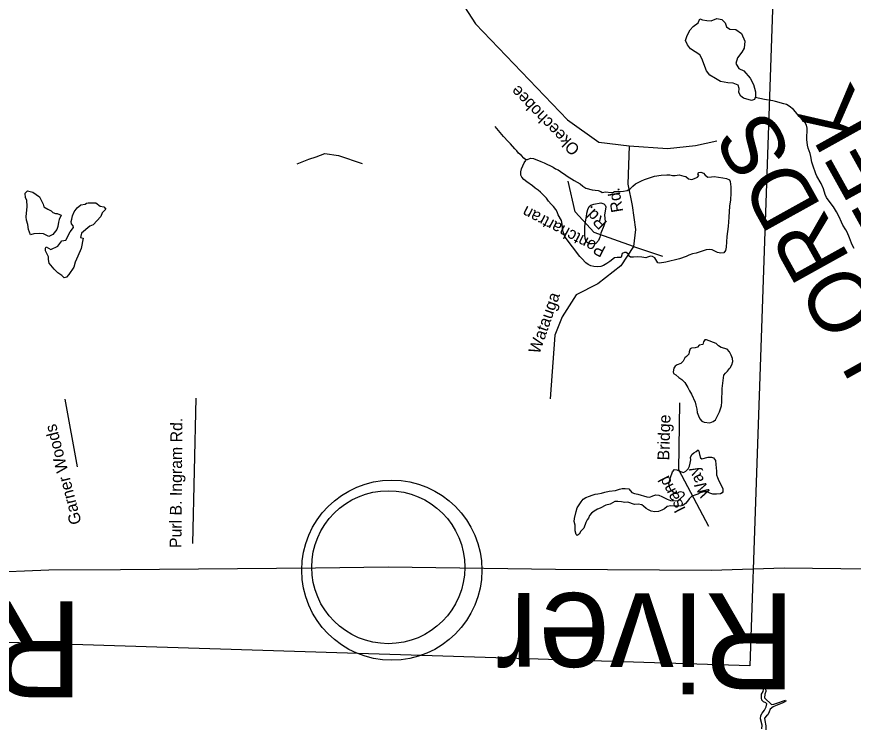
# Model space of a CAD drawing. Extents: x 2308163 to 2335412, y -96774 to 127732.
# Drawn here: x 2326125 to 2326219, y 122972.3 to 123052.3 of the extents above; entities that cross this region are included whole.
import ezdxf

# ---------------------------------------------------------------- set-up
doc = ezdxf.new("R2010")
doc.units = 0
for name, color, linetype in [('Default', 7, 'Continuous'), ('Old_Level_10', 7, 'Continuous'), ('Old_Level_11', 7, 'Continuous'), ('Old_Level_21', 7, 'Continuous'), ('Old_Level_32', 7, 'Continuous'), ('Old_Level_35', 7, 'Continuous'), ('Old_Level_59', 7, 'Continuous'), ('Old_Level_60', 7, 'Continuous'), ('Old_Level_61', 7, 'Continuous'), ('Old_Level_63', 7, 'Continuous')]:
    doc.layers.add(name, color=color, linetype=linetype)

msp = doc.modelspace()

# ---------------------------------------------------------------- linework, layer by layer
at = {"layer": 'Default'}
for centre, radius in [((2326167.157, 122990.014), 10.125), ((2326166.763, 122990.349), 8.606)]:
    msp.add_circle(centre, radius, dxfattribs=at)
at = {"layer": 'Old_Level_32'}
msp.add_lwpolyline([(2326240.144, 122990.411), (2326235.44, 122990.153), (2326232.787, 122990.142), (2326230.334, 122990.023), (2326211.264, 122990.222), (2326203.095, 122989.994), (2326185.551, 122990.089), (2326166.763, 122990.349), (2326158.564, 122990.222), (2326136.661, 122990.068), (2326128.602, 122990.027), (2326121.262, 122989.724), (2326120.231, 122989.721), (2326117.665, 122989.676)], dxfattribs=at)
at = {"layer": 'Old_Level_35'}
for points in [[(2326180.095, 123068.715), (2326178.579, 123066.219), (2326174.393, 123060.305), (2326173.511, 123057.806), (2326173.742, 123055.862), (2326176.57, 123051.446), (2326186.927, 123040.665), (2326190.418, 123038.162), (2326193.831, 123037.746), (2326198.142, 123037.449), (2326201.283, 123037.787), (2326203.685, 123038.3)], [(2326193.831, 123037.746), (2326193.682, 123033.433), (2326194.195, 123031.032), (2326194.549, 123028.34), (2326194.334, 123026.411), (2326192.917, 123024.226), (2326190.315, 123022.231), (2326187.888, 123020.975), (2326186.312, 123018.498), (2326185.496, 123016.441), (2326184.946, 123009.301)], [(2326156.532, 123035.701), (2326157.816, 123036.257), (2326158.664, 123036.518), (2326159.643, 123036.865), (2326161.161, 123036.665), (2326163.835, 123035.737)], [(2326194.334, 123026.411), (2326189.918, 123027.993), (2326187.762, 123030.301), (2326186.987, 123033.753)], [(2326194.334, 123026.411), (2326197.576, 123025.346)], [(2326131.815, 123001.644), (2326130.456, 123009.252)], [(2326144.78, 122993.006), (2326145.178, 123009.344)], [(2326202.786, 122994.937), (2326199.429, 123001.307), (2326199.531, 123008.825)]]:
    msp.add_lwpolyline(points, dxfattribs=at)
at = {"layer": 'Old_Level_59'}
for points in [[(2326217.159, 123030.315), (2326216.819, 123030.881), (2326216.192, 123031.68), (2326216.022, 123031.94), (2326215.883, 123032.249), (2326215.69, 123032.906), (2326215.417, 123033.495), (2326214.94, 123034.314), (2326214.813, 123034.603), (2326214.485, 123035.56), (2326214.393, 123035.913), (2326214.272, 123036.532), (2326214.188, 123036.865), (2326213.976, 123037.488), (2326213.902, 123037.815), (2326213.826, 123038.438), (2326213.84, 123039.728), (2326213.771, 123040.045), (2326213.616, 123040.325), (2326213.407, 123040.566), (2326212.944, 123041.044), (2326212.531, 123041.562), (2326212.3, 123041.808), (2326211.82, 123042.206), (2326211.537, 123042.384), (2326211.234, 123042.48), (2326210.305, 123042.721), (2326209.98, 123042.793), (2326209.058, 123042.936), (2326208.011, 123043.175)], [(2326182.201, 123036.19), (2326181.987, 123036.365), (2326181.731, 123036.659), (2326181.415, 123036.919), (2326181.222, 123037.174), (2326180.972, 123037.406), (2326180.513, 123037.956), (2326180.232, 123038.225), (2326179.697, 123038.797), (2326178.766, 123039.901)], [(2326219.117, 123026.198), (2326218.972, 123026.472), (2326218.84, 123026.787), (2326218.616, 123027.409), (2326218.338, 123028.018), (2326218.199, 123028.297), (2326217.868, 123028.822), (2326217.704, 123029.138), (2326217.443, 123029.751), (2326217.159, 123030.315)]]:
    msp.add_lwpolyline(points, dxfattribs=at)
at = {"layer": 'Old_Level_60'}
for points in [[(2326208.011, 123043.175), (2326207.928, 123042.94), (2326207.604, 123042.834), (2326206.696, 123043.094), (2326206.381, 123043.329), (2326206.151, 123043.743), (2326206.205, 123044.168), (2326206.084, 123044.553), (2326205.514, 123044.781), (2326204.947, 123044.836), (2326204.106, 123044.962), (2326203.563, 123045.321), (2326202.902, 123045.7), (2326202.517, 123046.165), (2326201.998, 123047.555), (2326201.777, 123047.984), (2326200.717, 123048.641), (2326200.415, 123049.098), (2326200.188, 123049.589), (2326200.346, 123050.157), (2326200.716, 123050.8), (2326201.035, 123051.15), (2326201.58, 123051.578), (2326201.767, 123052.039), (2326202.086, 123051.911), (2326202.589, 123051.823), (2326203.065, 123051.796), (2326203.707, 123052.069), (2326204.243, 123051.939), (2326204.624, 123051.56), (2326204.8, 123051.112), (2326205.173, 123050.85), (2326205.814, 123050.817), (2326206.453, 123050.374), (2326206.832, 123049.512), (2326206.776, 123048.721), (2326206.515, 123048.283), (2326206.013, 123047.64), (2326205.845, 123047.006), (2326206.167, 123046.451), (2326206.747, 123046.177), (2326207.44, 123045.345), (2326207.822, 123044.625), (2326208.05, 123043.82), (2326208.041, 123043.261), (2326208.011, 123043.175)], [(2326182.201, 123036.19), (2326182.424, 123036.198), (2326182.733, 123036.37), (2326183.068, 123036.308), (2326183.905, 123035.984), (2326184.275, 123035.824), (2326185.309, 123035.321), (2326185.569, 123035.159), (2326185.853, 123035.023), (2326186.124, 123034.866), (2326186.732, 123034.454), (2326186.977, 123034.262), (2326187.359, 123034.026), (2326187.671, 123033.857), (2326188.327, 123033.449), (2326188.626, 123033.21), (2326188.961, 123032.98), (2326189.677, 123032.797), (2326190.364, 123032.697), (2326190.672, 123032.6), (2326190.8, 123032.479), (2326191.193, 123032.562), (2326191.821, 123032.5), (2326191.998, 123032.504), (2326192.196, 123032.589), (2326192.852, 123032.591), (2326193.213, 123032.625), (2326193.629, 123032.702), (2326193.984, 123032.923), (2326194.242, 123033.209), (2326194.552, 123033.478), (2326195.219, 123033.805), (2326195.553, 123033.936), (2326195.915, 123034.051), (2326196.245, 123034.192), (2326196.701, 123034.339), (2326197.422, 123034.431), (2326198.064, 123034.485), (2326198.409, 123034.478), (2326198.706, 123034.407), (2326199.03, 123034.395), (2326199.445, 123034.462), (2326199.73, 123034.412), (2326200.003, 123034.316), (2326200.222, 123034.293), (2326200.505, 123034.03), (2326200.873, 123033.956), (2326201.175, 123034.047), (2326201.508, 123034.224), (2326201.672, 123034.386), (2326201.561, 123034.572), (2326201.686, 123034.726), (2326201.902, 123034.794), (2326202.18, 123034.663), (2326202.396, 123034.447), (2326202.676, 123034.214), (2326203.08, 123034.235), (2326203.413, 123034.29), (2326204.371, 123034.155), (2326204.789, 123034.07), (2326205.112, 123033.896), (2326205.212, 123033.715), (2326205.285, 123033.128), (2326205.268, 123032.397), (2326205.215, 123031.677), (2326205.137, 123030.948), (2326205.052, 123029.732), (2326204.961, 123028.683), (2326204.837, 123027.554), (2326204.738, 123026.348), (2326204.682, 123025.964), (2326204.498, 123025.686), (2326204.133, 123025.663), (2326203.783, 123025.746), (2326203.468, 123025.879), (2326203.167, 123026.047), (2326202.841, 123026.083), (2326202.484, 123026.035), (2326201.374, 123025.677), (2326200.956, 123025.584), (2326200.563, 123025.435), (2326200.23, 123025.279), (2326199.504, 123025.02), (2326197.979, 123024.666), (2326197.238, 123024.549), (2326197.053, 123024.566), (2326196.744, 123025.14), (2326196.452, 123025.298), (2326196.238, 123025.335), (2326195.92, 123025.235), (2326195.718, 123025.15), (2326195.259, 123025.232), (2326194.801, 123025.273), (2326194.342, 123025.218), (2326193.995, 123025.23), (2326193.842, 123025.347), (2326193.797, 123025.516), (2326193.49, 123025.725), (2326193.304, 123025.752), (2326193.069, 123025.618)], [(2326193.069, 123025.618), (2326192.95, 123025.23), (2326192.881, 123025.167), (2326192.497, 123025.17), (2326192.197, 123025.14), (2326191.683, 123024.73), (2326191.337, 123024.493), (2326190.944, 123024.294), (2326190.637, 123024.172), (2326190.276, 123024.139), (2326189.877, 123024.163), (2326189.524, 123024.246), (2326189.224, 123024.378), (2326188.981, 123024.58), (2326188.507, 123025.053), (2326188.3, 123025.289), (2326186.66, 123027.475), (2326186.497, 123027.826), (2326186.374, 123028.191), (2326186.353, 123028.598), (2326186.308, 123028.935), (2326186.218, 123029.334), (2326185.871, 123029.987), (2326185.751, 123030.301), (2326185.587, 123030.591), (2326185.346, 123030.914), (2326185.06, 123031.183), (2326184.791, 123031.497), (2326184.542, 123031.846), (2326183.885, 123032.514), (2326183.62, 123032.747), (2326183.256, 123032.983), (2326182.961, 123033.253), (2326182.323, 123033.686), (2326182.009, 123033.936), (2326181.765, 123034.224), (2326181.646, 123034.446), (2326181.679, 123034.806), (2326181.756, 123035.149), (2326181.888, 123035.495), (2326182.044, 123035.835), (2326182.208, 123036.104), (2326182.201, 123036.19)], [(2326135.018, 123030.6), (2326134.588, 123030.199), (2326134.463, 123029.773), (2326133.585, 123028.861), (2326133.205, 123028.707), (2326132.275, 123027.907), (2326132.175, 123027.411), (2326132.451, 123027.36), (2326132.229, 123026.175), (2326131.867, 123025.314), (2326131.566, 123024.658), (2326131.423, 123024.108), (2326130.852, 123023.254), (2326130.579, 123022.986), (2326130.34, 123022.898), (2326130.072, 123023.17), (2326129.624, 123023.463), (2326129.208, 123023.88), (2326128.635, 123024.551), (2326128.565, 123024.942), (2326128.562, 123025.261), (2326128.224, 123025.925), (2326128.234, 123026.216), (2326128.31, 123026.393), (2326128.813, 123026.085), (2326129.603, 123026.46), (2326130.081, 123027.053), (2326130.5, 123027.136), (2326130.989, 123028.049), (2326131.368, 123028.563), (2326131.347, 123028.757), (2326131.16, 123028.972), (2326131.114, 123029.237), (2326131.178, 123029.498), (2326131.247, 123029.87), (2326131.442, 123030.308), (2326131.791, 123030.781), (2326132.19, 123031.086), (2326132.693, 123031.18), (2326132.822, 123031.3), (2326133.018, 123031.335), (2326133.906, 123031.332), (2326134.392, 123030.941), (2326134.778, 123030.872), (2326135.018, 123030.6)], [(2326205.482, 123013.493), (2326205.447, 123013.839), (2326205.305, 123014.21), (2326205.114, 123014.552), (2326204.865, 123014.866), (2326204.169, 123015.072), (2326203.89, 123015.255), (2326203.624, 123015.503), (2326202.527, 123015.922), (2326202.339, 123015.933), (2326202.199, 123015.709), (2326202.135, 123015.407), (2326201.702, 123015.32), (2326201.515, 123015.083), (2326201.278, 123015.01), (2326200.861, 123014.999), (2326200.69, 123014.913), (2326200.577, 123014.587), (2326200.545, 123014.308), (2326200.276, 123014.053), (2326200.092, 123013.902), (2326199.926, 123013.527), (2326199.663, 123013.251), (2326199.247, 123013.098), (2326198.996, 123012.944), (2326198.874, 123012.725), (2326198.802, 123012.331), (2326198.842, 123012.152), (2326199.092, 123011.97), (2326199.412, 123011.695), (2326199.764, 123011.469), (2326200.105, 123011.112), (2326200.442, 123010.552), (2326200.614, 123010.175), (2326200.832, 123009.791), (2326201.241, 123008.913), (2326201.349, 123008.574), (2326201.441, 123008.129), (2326201.485, 123007.736), (2326201.633, 123007.365), (2326201.798, 123007.05), (2326202.012, 123006.768), (2326202.264, 123006.648), (2326202.92, 123006.579), (2326203.292, 123006.734), (2326203.534, 123006.934), (2326203.703, 123007.228), (2326204.006, 123007.832), (2326204.214, 123008.481), (2326204.264, 123008.941), (2326204.299, 123010.439), (2326204.432, 123011.629), (2326204.483, 123011.942), (2326204.685, 123012.179), (2326204.906, 123012.4), (2326205.12, 123012.707), (2326205.193, 123012.781), (2326205.384, 123013.12), (2326205.482, 123013.493)], [(2326187.768, 122995.08), (2326187.646, 122995.48), (2326187.697, 122995.844), (2326187.866, 122996.606), (2326188.012, 122997.033), (2326188.462, 122997.708), (2326188.68, 122997.995), (2326188.979, 122998.198), (2326189.396, 122998.321), (2326189.695, 122998.448), (2326190, 122998.549), (2326190.307, 122998.615), (2326190.723, 122998.672), (2326191.107, 122998.781), (2326191.603, 122998.89), (2326192.318, 122998.993), (2326192.739, 122999.126), (2326193.04, 122999.192), (2326193.375, 122999.195), (2326193.813, 122999.145), (2326194.146, 122998.747), (2326194.445, 122998.62), (2326194.797, 122998.577), (2326195.845, 122998.246), (2326196.169, 122998.21), (2326196.516, 122998.376), (2326196.843, 122998.506), (2326197.167, 122998.455), (2326197.525, 122998.305), (2326198.12, 122997.99), (2326198.471, 122997.846), (2326199.086, 122997.824), (2326199.362, 122997.856), (2326199.605, 122998.091), (2326199.999, 122998.413), (2326200.042, 122998.599), (2326199.956, 122998.755), (2326199.615, 122998.843), (2326199.416, 122998.779), (2326199.301, 122998.686), (2326198.906, 122998.73), (2326198.577, 122998.985), (2326198.366, 122999.343), (2326198.307, 122999.757), (2326198.475, 123000.432), (2326198.694, 123001.085), (2326198.936, 123001.325), (2326199.2, 123001.311), (2326199.616, 123001.109), (2326199.941, 123000.986), (2326200.223, 123001.144), (2326200.483, 123001.43), (2326200.617, 123001.72), (2326200.711, 123002.052), (2326200.759, 123002.436), (2326200.745, 123002.676), (2326200.897, 123003.006), (2326201.112, 123003.227), (2326201.36, 123003.376), (2326201.592, 123003.536), (2326201.683, 123003.416), (2326201.765, 123003.011), (2326201.862, 123002.657), (2326202.024, 123002.555), (2326202.733, 123002.729), (2326203.088, 123002.722), (2326203.319, 123002.638), (2326203.536, 123002.341), (2326203.601, 123001.901), (2326203.657, 123001.132), (2326203.67, 123000.74), (2326203.767, 123000.432), (2326203.931, 123000.061), (2326204.227, 122999.492), (2326204.351, 122999.152), (2326204.375, 122998.836), (2326204.307, 122998.701), (2326204.089, 122998.607), (2326203.676, 122998.555), (2326203.244, 122998.58), (2326202.904, 122998.684), (2326202.618, 122998.815), (2326202.198, 122998.835), (2326201.836, 122998.715), (2326201.546, 122998.558), (2326201.206, 122998.468), (2326200.852, 122998.287), (2326200.593, 122998.037), (2326200.405, 122997.774), (2326200.177, 122997.528), (2326199.883, 122997.304), (2326199.581, 122997.213), (2326198.521, 122997.244), (2326198.108, 122997.162), (2326197.795, 122996.924), (2326197.527, 122996.765), (2326197.15, 122996.606), (2326196.742, 122996.569), (2326196.319, 122996.634), (2326196.016, 122996.792)], [(2326196.016, 122996.792), (2326195.737, 122996.959), (2326195.47, 122997.223), (2326195.267, 122997.362), (2326194.865, 122997.431), (2326194.429, 122997.386), (2326193.678, 122997.665), (2326193.349, 122997.611), (2326192.997, 122997.704), (2326192.557, 122997.75), (2326192.236, 122997.751), (2326191.964, 122997.582), (2326191.699, 122997.444), (2326191.211, 122997.319), (2326190.563, 122996.97), (2326190.275, 122996.868), (2326189.92, 122996.662), (2326189.601, 122996.419), (2326189.377, 122996.173), (2326189.287, 122995.871), (2326189.122, 122995.678), (2326188.982, 122995.383), (2326188.75, 122994.726), (2326188.395, 122994.403), (2326188.227, 122994.073), (2326187.995, 122993.924), (2326187.866, 122994.014), (2326187.777, 122994.454), (2326187.761, 122994.801), (2326187.768, 122995.08)], [(2326208.744, 122972.172), (2326208.78, 122972.567), (2326208.587, 122973.285), (2326208.653, 122973.669), (2326208.794, 122973.939), (2326209.039, 122974.265), (2326209.235, 122974.645), (2326209.334, 122974.977), (2326209.218, 122975.093), (2326208.924, 122975.215), (2326208.753, 122975.398), (2326208.707, 122975.649), (2326208.718, 122976.07), (2326208.901, 122976.379), (2326208.935, 122976.606), (2326208.744, 122976.948), (2326208.52, 122977.251), (2326208.778, 122977.516), (2326208.817, 122977.174), (2326208.968, 122977.032), (2326209.158, 122976.71), (2326209.211, 122976.358), (2326209.103, 122976.057), (2326209.049, 122975.673), (2326209.102, 122975.605), (2326209.838, 122974.919), (2326210.091, 122974.93), (2326210.432, 122975.046), (2326210.77, 122975.186), (2326211.084, 122975.277), (2326211.404, 122975.403), (2326211.433, 122975.301), (2326211.332, 122975.203), (2326211.034, 122975.04), (2326210.355, 122974.81), (2326210.014, 122974.643), (2326209.672, 122974.396), (2326209.582, 122974.094), (2326209.442, 122973.733), (2326209.282, 122973.637), (2326209.067, 122973.365), (2326209.077, 122973.121), (2326209.191, 122972.517), (2326209.21, 122972.075)]]:
    msp.add_lwpolyline(points, dxfattribs=at)
msp.add_lwpolyline([(2326129.985, 123029.953), (2326129.75, 123029.471), (2326129.685, 123029.147), (2326129.614, 123028.66), (2326129.494, 123028.338), (2326129.038, 123027.755), (2326128.595, 123027.552), (2326128.006, 123027.845), (2326127.517, 123027.862), (2326126.916, 123027.828), (2326126.532, 123027.732), (2326126.335, 123028.338), (2326126.245, 123028.885), (2326126.099, 123029.38), (2326126.057, 123029.762), (2326126.151, 123030.902), (2326126.121, 123031.61), (2326125.967, 123031.887), (2326125.932, 123032.433), (2326126.213, 123032.695), (2326126.806, 123032.511), (2326127.55, 123031.996), (2326127.957, 123031.166), (2326128.057, 123030.89), (2326128.482, 123030.603), (2326128.858, 123030.427), (2326129.07, 123030.257), (2326129.338, 123030.139), (2326129.555, 123030.131)], close=True, dxfattribs=at)
at = {"layer": 'Old_Level_61'}
msp.add_lwpolyline([(2326191.226, 123030.864), (2326191.153, 123030.389), (2326191.067, 123029.965), (2326191.156, 123029.179), (2326191.006, 123028.742), (2326190.652, 123027.906), (2326190.56, 123027.457), (2326190.411, 123027.086), (2326190.092, 123026.757), (2326189.672, 123026.705), (2326189.343, 123026.722), (2326189.012, 123026.952), (2326188.895, 123027.332), (2326188.861, 123027.719), (2326188.861, 123028.583), (2326188.881, 123029.009), (2326189.026, 123029.796), (2326189.074, 123030.176), (2326189.181, 123030.563), (2326189.36, 123030.928), (2326189.521, 123031.065), (2326189.883, 123031.169), (2326190.664, 123031.31), (2326190.999, 123031.227), (2326191.157, 123031.059), (2326191.226, 123030.864)], dxfattribs=at)
at = {"layer": 'Old_Level_63'}
msp.add_lwpolyline([(2326216.613, 123246.241), (2326207.405, 122979.252), (2326040.737, 122984.512), (2326051.481, 123296.047)], dxfattribs=at)

# ---------------------------------------------------------------- texts
at = {"layer": 'Old_Level_10'}
for s, height, rotation, p in [('Okeechobee', 1.3328, 134.28981, (2326188.394, 123037.428)), ('Rd.', 1.3328, 99.38949, (2326193.168, 123030.358)), ('Pontchartran', 1.33284, 152.53167, (2326191.32, 123026.323)), ('Rd.', 1.3328, 134.45661, (2326191.456, 123029.114)), ('Watauga', 1.3328, 70.85287, (2326183.742, 123014.243)), ('Bridge', 1.3328, 88.41707, (2326198.348, 123002.347)), ('Garner Woods', 1.33284, 104.4911, (2326132.298, 122995.332)), ('Purl B. Ingram Rd.', 1.33284, 89.57339, (2326143.51, 122992.497)), ('Way', 1.3328, 117.30098, (2326203.072, 122998.658)), ('Isand', 1.3328, 117.30098, (2326200.228, 122996.904))]:
    msp.add_text(s, height=height, rotation=rotation, dxfattribs=at).set_placement(p)
at = {"layer": 'Old_Level_11'}
for s, p in [('River', (2326212.514, 122987.402)), ('Rd.', (2326132.443, 122986.512))]:
    msp.add_text(s, height=10.796, rotation=179.92563, dxfattribs=at).set_placement(p)
at = {"layer": 'Old_Level_21'}
for s, p in [('CREEK', (2326234.09, 123017.268)), ('LORDS', (2326224.759, 123014.253))]:
    msp.add_text(s, height=6.9062, rotation=119.04569, dxfattribs=at).set_placement(p)

doc.saveas('drawing.dxf')
